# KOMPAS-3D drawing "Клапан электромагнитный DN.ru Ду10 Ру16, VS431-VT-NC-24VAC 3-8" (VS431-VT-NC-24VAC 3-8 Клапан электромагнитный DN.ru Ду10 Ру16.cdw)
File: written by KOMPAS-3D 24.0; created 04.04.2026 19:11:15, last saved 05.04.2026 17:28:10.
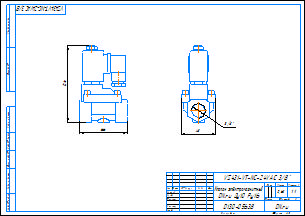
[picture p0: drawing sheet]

Document properties: c3d_UniqueCompID: ef56311e-7521-43dc-8291-0e6108b3d81d; Обозначение: VS400-ET-NC-220VAC 3-8; Наименование: Клапан электромагнитный DN.ru Ду10 Ру16; Автор: artio; Класс точности: c; Знак неуказанной шероховатости: Шероховатость не задана; Рассекать на разрезах: Да; Автор: artio; Форматы листов документа: A3; Полное имя файла: VS431-VT-NC-24VAC 3-8 Клапан электромагнитный DN.ru Ду10 Ру16.m3d; Масса: 0.62; Наименование: Клапан электромагнитный DN.ru Ду10 Ру16; Количество листов документа: 1; Примечание: D130-05638

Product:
- Body: Тело 1  | qty 1
    Масса: 1.030062
- Part/product: Клапан электромагнитный DN.ru Ду10 Ру16  | designation VS431-VT-NC-24VAC 3-8
    Масса: 0.62
    Раздел спецификации: Прочие изделия
    Примечание: D130-05638
    additional columns: ef56311e-7521-43dc-8291-0e6108b3d81d; VS400-ET-NC-220VAC 3-8; artio; c; Шероховатость не задана; Да

Views: Вид 1, Спереди, Проекционный вид 2
Referenced files in C:\Users\artio\OneDrive\Рабочий стол\Клапан электромагнитный DN.ru\VS400-ET-NC\VS400-ET-NC-24VDC\: VS400-ET-NC-24VDC 3-8 Клапан электромагнитный DN.ru Ду10 Ру16.m3d
Referenced files in C:\Users\artio\OneDrive\Рабочий стол\Клапан электромагнитный DN.ru\VS431\VS431-VT-NC\VS431-VT-NC-24VAC\Ду10\: VS431-VT-NC-24VAC 3-8 Клапан электромагнитный DN.ru Ду10 Ру16.m3d
Referenced files in C:\Users\artio\OneDrive\Рабочий стол\Клапан электромагнитный DN.ru\VS400-ET-NC\: VS400-ET-NC-24VDC 3-8 Клапан электромагнитный DN.ru Ду10 Ру16.cdw
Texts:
  VS431-VT-NC-24VAC 3-8
  Клапан электромагнитный
  DN.ru Ду10 Ру16
  VS431-VT-NC-24VAC 3/8"
  VS431-VT-NC-24VAC 3/8"-
  Клапан электромагнитный DN.ru Ду10 Ру16
  VS431-VT-NC-24VAC 3-8 Клапан электромагнитный DN.ru Ду10 Ру16
Dimensions and other numbers on the sheet: 0; 3; 2; 4; 48; 3/8"; 66; 106; 1:1; 1; 0,62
